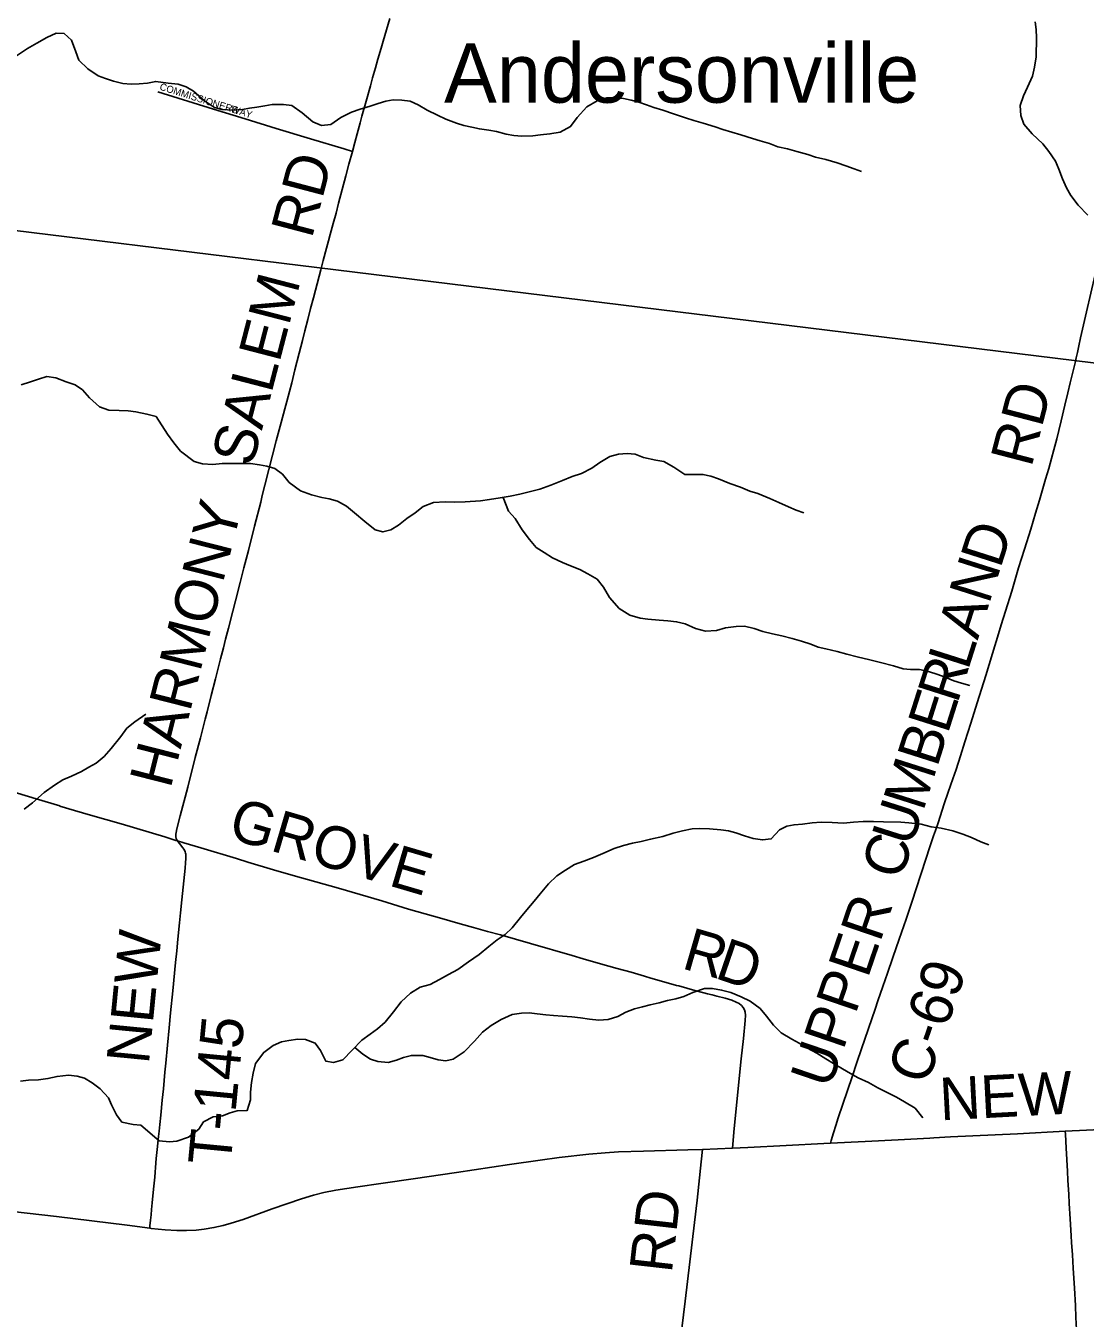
# Model space of a CAD drawing. Extents: x 1451455 to 1749751, y 218250 to 574981.
# Drawn here: x 1541480 to 1548942, y 371806 to 380909 of the extents above; entities that cross this region are included whole.
import ezdxf

# ---------------------------------------------------------------- set-up
doc = ezdxf.new("R2010")
doc.units = 0
for name, color, linetype in [('GM_X_County_Road', 7, 'Continuous'), ('GM_X_County_Road_Text', 7, 'Continuous'), ('GM_X_Minor_River', 7, 'Continuous'), ('GM_X_Township', 7, 'Continuous'), ('GM_X_Township_Road', 7, 'Continuous'), ('GM_X_Township_Road_Text', 7, 'Continuous'), ('GM_X_Township_Subdivision', 7, 'Continuous'), ('GM_X_Township_Subdivision_Text', 7, 'Continuous'), ('GM_X_Unincorporated_Text', 7, 'Continuous')]:
    doc.layers.add(name, color=color, linetype=linetype)

msp = doc.modelspace()

# ---------------------------------------------------------------- linework, layer by layer
at = {"layer": 'GM_X_County_Road'}
for points in [[(1548873.5, 378545.7), (1548879.2, 378569.3), (1548887.8, 378608.4), (1548897.9, 378654.2), (1548908.6, 378711.8), (1548922.1, 378772.3), (1548936.7, 378833.3), (1548958.7, 378925.8), (1548974.5, 378994.8), (1548988.8, 379056.9), (1549022.5, 379196.3), (1549040.4, 379268.8), (1549057.9, 379348.9), (1549072.7, 379416.2), (1549100.4, 379540), (1549121.8, 379635.1), (1549147.3, 379744.1), (1549180.4, 379885.5), (1549206.4, 379999), (1549236.1, 380128.4), (1549268.1, 380264.2), (1549292.4, 380367), (1549317, 380471.5)], [(1547147.2, 373038.2), (1547152.9, 373057.3), (1547169.4, 373112), (1547185, 373163.5), (1547202.1, 373217.2), (1547234.4, 373313.8), (1547300, 373505.5), (1547334.4, 373606.2), (1547367.2, 373703.5), (1547461.8, 373983.7), (1547480.9, 374041), (1547517, 374142.8), (1547548.5, 374235.3), (1547586.4, 374346.6), (1547630.5, 374476), (1547680, 374616.8), (1547721.7, 374735.3), (1547784.5, 374931.2), (1547822.6, 375047.3), (1547846.2, 375119.4), (1547874.4, 375202.6), (1547887.1, 375241), (1547905.2, 375296), (1547949.7, 375429.9), (1547977.7, 375510.7), (1548010.7, 375605.4), (1548032, 375669.7), (1548064.4, 375767.4), (1548094.8, 375865), (1548136, 375997.2), (1548180.5, 376141.3), (1548241.2, 376332.2), (1548289.5, 376488.7), (1548331.7, 376626.6), (1548351, 376690.7), (1548380, 376786.9), (1548424.1, 376927.7), (1548473.1, 377091.2), (1548514.8, 377222.4), (1548558.2, 377364), (1548592.1, 377476.4), (1548619.5, 377568.3), (1548662.6, 377715.6), (1548684.6, 377790.8), (1548705.6, 377862.3), (1548721.8, 377922.8), (1548742.8, 378000.7), (1548756.9, 378057.5), (1548773.3, 378125.9), (1548799.5, 378236.5), (1548820.3, 378323.4), (1548837.1, 378394), (1548850.7, 378451), (1548873.5, 378545.7)], [(1548801, 373122.4), (1549252.4, 373145.1), (1549350.6, 373149.5), (1549819.2, 373172.1), (1550087.9, 373185.7), (1550484.4, 373205.5), (1550772.6, 373219.9), (1551224.9, 373239.8), (1551618.1, 373259.5), (1551870.3, 373274.6), (1551912.6, 373278.1), (1552036.7, 373287.1), (1552088.9, 373291.6), (1552235.8, 373303.9), (1552340.2, 373313.9), (1552692.8, 373348.3), (1553146.4, 373394.4), (1553290.1, 373408.3), (1553476.1, 373426.5), (1553538.1, 373433.7), (1553560.3, 373435.7), (1553575.3, 373433.8), (1553584, 373430)], [(1547147.2, 373038.2), (1547391.6, 373050.4), (1547624.2, 373062.3), (1547846.9, 373074.6), (1547876.3, 373076.6), (1547994.1, 373082.6), (1548466, 373105.6), (1548801, 373122.4)], [(1546457.2, 373003.3), (1546565.4, 373007.7), (1546834.6, 373021.8), (1547100.1, 373035.8), (1547147.2, 373038.2)], [(1542353.1, 372440.2), (1542362.5, 372439), (1542460.7, 372429.1), (1542542.8, 372424.3), (1542611.9, 372424), (1542681, 372427.2), (1542736.7, 372433.2), (1542805, 372444.5), (1542869.4, 372458.2), (1542926.4, 372474.4), (1543010.7, 372502.3), (1543214.3, 372576), (1543421.8, 372648), (1543506.3, 372673.6), (1543579.4, 372691.3), (1543663, 372707), (1543818.5, 372730.9), (1543980.8, 372754.5), (1544224.2, 372791), (1544305.2, 372803), (1544513.1, 372832.9), (1544886.2, 372888.2), (1545103.7, 372919.9), (1545237, 372937.2), (1545445.5, 372960.9), (1545559.7, 372971.4), (1545654.5, 372977.2), (1545831.5, 372983.6), (1546142.7, 372992.4), (1546246.9, 372995.5)], [(1546101.2, 371734.6), (1546124.2, 371926.7), (1546189.4, 372480.7), (1546207.7, 372637), (1546236.4, 372907), (1546246.9, 372995.5)], [(1546246.9, 372995.5), (1546457.2, 373003.3)], [(1540435, 372667.6), (1540473.7, 372663.7), (1540515.7, 372659.5), (1540586.2, 372650.4), (1540751.6, 372630.6), (1540874, 372615.9), (1540971.8, 372605.3), (1541695.2, 372522), (1542193.4, 372461.5), (1542353.1, 372440.2)]]:
    msp.add_lwpolyline(points, dxfattribs=at)
at = {"layer": 'GM_X_Minor_River'}
for points in [[(1548590.6, 380937.3), (1548595.7, 380883.2), (1548598.7, 380825.1), (1548596.5, 380691.1), (1548585.3, 380617.2), (1548570.3, 380555.4), (1548535.1, 380477.9), (1548508.1, 380416.3), (1548485, 380348.6), (1548487.8, 380276.6), (1548508.8, 380216.2), (1548567.6, 380149.2), (1548644.3, 380078), (1548685.4, 380023.3), (1548732.2, 379954.5), (1548755.2, 379898.1), (1548782.1, 379831.6), (1548811, 379767.1), (1548840, 379714.6), (1548892.8, 379645.8), (1548959.6, 379574.6)], [(1541407, 380691.9), (1541492, 380748.5), (1541558.7, 380787.5), (1541629.3, 380826.4), (1541693.9, 380857.3), (1541749.8, 380854.4), (1541803, 380807.4), (1541831.6, 380726.8), (1541854.5, 380666.3), (1541917.4, 380605.2), (1541990.5, 380555.9), (1542042.2, 380537), (1542097.9, 380520), (1542163.6, 380502.9), (1542221.5, 380497.9), (1542277.5, 380501), (1542337.6, 380506), (1542395.8, 380517), (1542483.8, 380504.5)], [(1542483.8, 380504.5), (1542553.6, 380497.4), (1542609.2, 380478.5), (1542660.7, 380449.6), (1542739.4, 380380.3), (1542808.5, 380333.2), (1542864.2, 380320.3), (1542938, 380315.1), (1543006, 380320), (1543056.1, 380329.2), (1543106.2, 380336.5), (1543164.2, 380345.5), (1543216.3, 380354.7), (1543294.2, 380355.5), (1543354, 380348.5), (1543427, 380295.3), (1543501.9, 380232.1), (1543563.4, 380207.1), (1543627.4, 380214.1), (1543698.1, 380263), (1543774.6, 380299.8), (1543834.9, 380320.8), (1543905.2, 380343.7), (1543961.4, 380360.8), (1544015.6, 380377.9), (1544067.7, 380387.1), (1544129.6, 380386.1), (1544187.3, 380377.2), (1544244.8, 380352.3), (1544308.2, 380315.2), (1544379.5, 380280.1), (1544438.9, 380251.1), (1544514.4, 380223.9), (1544566, 380207.1), (1544621.7, 380194.2), (1544675.5, 380183.3), (1544741.2, 380174.2), (1544795, 380165.4), (1544864.6, 380146.3), (1544916.4, 380137.4), (1544974.2, 380132.5), (1545052.1, 380133.3), (1545106.2, 380140.4), (1545172.2, 380147.3), (1545244.3, 380160.2), (1545316.8, 380199.1), (1545363.9, 380264.3), (1545431, 380339.3), (1545503.6, 380380.2), (1545571.8, 380401.1), (1545627.8, 380402.2), (1545689.6, 380397.2), (1545743.3, 380386.4), (1545797, 380371.5), (1545852.6, 380352.6), (1545904.3, 380333.8), (1545965.9, 380314.8), (1546041.3, 380289.5), (1546126.7, 380260.2), (1546184.4, 380243.2), (1546249.9, 380222.2), (1546335.4, 380196.8), (1546389, 380177.9), (1546452.6, 380160.9), (1546516.2, 380141.9), (1546597.7, 380114.6), (1546653.4, 380099.7), (1546719, 380080.6), (1546776.5, 380057.7), (1546844.2, 380042.6), (1546909.8, 380023.5), (1546987.3, 380002.3), (1547042.9, 379983.4), (1547114.6, 379968.3), (1547194, 379943), (1547255.6, 379922), (1547315.2, 379901), (1547366.8, 379882.2)], [(1541446.9, 378379.4), (1541513.2, 378400.3), (1541569.6, 378419.4), (1541627.9, 378438.5), (1541691.7, 378429.4), (1541765.2, 378402.1), (1541828.8, 378381), (1541880.2, 378344.1), (1541929.2, 378289.2), (1541998.1, 378225.9), (1542065.7, 378200.8), (1542137.6, 378199.6), (1542201.5, 378196.5)], [(1542201.5, 378196.5), (1542255.4, 378189.6), (1542333.1, 378174.2), (1542398.8, 378157.1)], [(1542398.8, 378157.1), (1542479, 378033.2), (1542522, 377972.5), (1542569, 377913.7), (1542665.6, 377840.1), (1542725.2, 377823.2), (1542797, 377818), (1542863.1, 377825), (1542937, 377825.8), (1542998.9, 377826.8), (1543062.8, 377825.8), (1543126.6, 377816.7), (1543178.4, 377807.9), (1543234, 377791), (1543287.3, 377752.1), (1543336.2, 377693.3), (1543415.2, 377634), (1543492.6, 377604.8), (1543564.2, 377587.6), (1543615.9, 377576.8), (1543675.6, 377559.8), (1543738.9, 377526.8), (1543796.1, 377479.8), (1543869, 377418.7), (1543941.9, 377359.5), (1543995.6, 377344.6), (1544051.7, 377359.7), (1544104.2, 377392.9), (1544164.9, 377437.9), (1544221.5, 377479.1), (1544278.1, 377522.2), (1544352.5, 377551), (1544434.4, 377555.7), (1544498.3, 377554.7), (1544574.2, 377555.5), (1544682.2, 377563.7), (1544746.3, 377572.7), (1544820.4, 377583.5), (1544892.5, 377596.4), (1544960.6, 377611.3), (1545101, 377645.1), (1545177.4, 377673.9), (1545259.8, 377706.6), (1545328.1, 377733.5), (1545394.4, 377756.5), (1545466.9, 377793.3), (1545523.5, 377832.5), (1545594.1, 377875.3), (1545654.3, 377892.4), (1545716.3, 377897.4), (1545772.1, 377892.5), (1545831.7, 377869.5), (1545917.2, 377850.2), (1545975, 377839.2), (1546044.2, 377800.1), (1546121.3, 377748.9), (1546175.2, 377748), (1546249.1, 377748.8), (1546304.8, 377737.9), (1546358.4, 377717), (1546437.8, 377685.8), (1546513.3, 377658.5), (1546578.7, 377631.5), (1546636.4, 377614.6), (1546721.7, 377579.2), (1546783.1, 377552.2), (1546852.5, 377521.1), (1546906.1, 377498.2), (1546959.7, 377479.3)], [(1544842.2, 377587.5), (1544880.7, 377490.5), (1544925.8, 377437.8), (1544976.4, 377358.9), (1545027.2, 377290.1), (1545074.3, 377235.3), (1545131.6, 377198.4), (1545190.9, 377161.4), (1545260.2, 377128.3), (1545317.8, 377105.3), (1545381.3, 377080.3), (1545438.7, 377049.4), (1545504, 377010.3), (1545549, 376955.5), (1545591.7, 376882.8), (1545658.4, 376805.7), (1545735.5, 376758.5), (1545807, 376737.3), (1545860.8, 376730.5), (1545940.6, 376723.2), (1546002.4, 376718.2), (1546064.2, 376711.2), (1546123.9, 376696.2), (1546197.3, 376665), (1546266.9, 376645.9), (1546344.9, 376650.7), (1546409, 376667.7), (1546483.1, 376678.5), (1546543.1, 376679.5), (1546610.7, 376664.4), (1546670.3, 376643.5), (1546739.9, 376626.3), (1546805.6, 376611.3), (1546877.2, 376594.1), (1546942.8, 376575.1), (1547008.3, 376554), (1547061.9, 376533.2), (1547115.6, 376520.3), (1547195.2, 376501), (1547262.8, 376483.9), (1547336.4, 376464.7), (1547423.9, 376443.3), (1547499.5, 376424.1), (1547591, 376400.6), (1547660.6, 376379.5), (1547712.4, 376374.7), (1547774.3, 376375.7), (1547828.1, 376362.8), (1547883.7, 376345.9), (1547943.3, 376325), (1548016.7, 376295.8), (1548070.3, 376278.9), (1548130, 376262)], [(1541469.1, 375392.1), (1541527.8, 375437.2), (1541609, 375508), (1541681.9, 375560.8), (1541740.6, 375597.9), (1541803, 375624.9), (1541871.6, 375657.8), (1541924.1, 375687), (1541974.6, 375716.2), (1542031.3, 375761.3), (1542080.3, 375818.6), (1542149.8, 375903.5), (1542192.8, 375960.9), (1542247.5, 376006.1), (1542324.5, 376060.9)], [(1542290.2, 373164.6), (1542419.1, 373055.4), (1542492.9, 373048.2), (1542542.9, 373053.4), (1542625.2, 373082.1), (1542698, 373137), (1542732.8, 373188.5), (1542799.3, 373225.4), (1542865.3, 373230.4), (1542919.6, 373251.5), (1542969.8, 373266.7), (1543039.7, 373269.6), (1543062.9, 373343.3), (1543063.8, 373399.3), (1543070.9, 373465.2), (1543082, 373533.1), (1543099.1, 373600.8), (1543156.3, 373678), (1543223, 373726.9), (1543281.3, 373752), (1543333.5, 373763.2), (1543395.5, 373772.2), (1543449.4, 373769.3), (1543518.9, 373744.2), (1543556, 373691.6), (1543592.7, 373617), (1543648.4, 373606), (1543712.6, 373625), (1543777.7, 373694), (1543846.8, 373765), (1543905.4, 373806.1), (1543957.9, 373845.2), (1544010.6, 373890.4), (1544069.7, 373963.5), (1544122.8, 374034.7), (1544189.7, 374095.7), (1544258.3, 374136.6), (1544328.6, 374157.5), (1544395.1, 374192.5), (1544457.5, 374227.5), (1544522, 374262.5), (1544598.8, 374315.3), (1544673.6, 374368.1), (1544742.4, 374425), (1544799.1, 374470.1), (1544855.6, 374509.3), (1544906.3, 374556.5), (1544965.5, 374629.6), (1545008.3, 374682.9), (1545061.2, 374744.1), (1545104, 374795.5), (1545161.1, 374864.6), (1545219.9, 374921.7), (1545280.5, 374962.7), (1545345.1, 375001.7), (1545411.3, 375024.7), (1545479.7, 375051.6), (1545544, 375078.6), (1545624.5, 375113.3), (1545690.8, 375136.3), (1545753, 375151.3), (1545815.1, 375164.3), (1545881.2, 375179.2), (1545967.5, 375199.9), (1546039.7, 375222.7), (1546105.9, 375239.7), (1546174, 375252.6), (1546226, 375255.8), (1546295.9, 375252.7), (1546375.6, 375245.4), (1546429.5, 375238.5), (1546481.1, 375223.7), (1546542.7, 375202.7), (1546602.3, 375185.7), (1546668.1, 375174.7), (1546730.1, 375181.7), (1546789.1, 375244.8), (1546841.4, 375272), (1546891.5, 375281.2), (1546951.5, 375286.2), (1547019.6, 375295.1), (1547081.6, 375300.1), (1547159.4, 375296.9), (1547239.2, 375293.6), (1547309.3, 375300.5), (1547379.2, 375305.4), (1547451.1, 375304.2), (1547521, 375301.1), (1547642.8, 375299.2), (1547700.6, 375296.3), (1547786.3, 375284.9), (1547856, 375267.8), (1547927.7, 375256.6), (1548009.3, 375239.3), (1548080.8, 375216.1), (1548140.3, 375191.2), (1548205.7, 375162.1), (1548263.3, 375139.2)], [(1543796.6, 373713.5), (1543853.1, 373664.8), (1543908.5, 373629.9), (1543960.1, 373613.1), (1544031.9, 373607.9), (1544090.1, 373623), (1544140.3, 373642.2), (1544196.5, 373657.3), (1544276.4, 373656), (1544328.1, 373643.2), (1544383.7, 373626.3), (1544439.5, 373619.4), (1544489.7, 373630.6), (1544568.4, 373683.4), (1544639.5, 373758.3), (1544696.5, 373821.4), (1544757.2, 373868.5), (1544827.8, 373909.4), (1544906.2, 373944.1), (1544972.3, 373955.1), (1545026.3, 373956.2), (1545082.1, 373949.3), (1545143.9, 373942.3), (1545197.7, 373937.5), (1545259.6, 373934.5), (1545325.4, 373929.4), (1545387.2, 373922.4), (1545451, 373913.4), (1545516.7, 373904.4), (1545582.7, 373909.3), (1545649, 373930.3), (1545705.4, 373961.4), (1545767.7, 373984.4), (1545823.9, 373999.5), (1545878, 374012.6), (1545940.2, 374027.7), (1546000.3, 374042.7), (1546058.5, 374055.8), (1546114.6, 374070.9), (1546179, 374099.9), (1546261.4, 374128.6), (1546317.3, 374127.7), (1546381, 374116.7), (1546446.6, 374099.6), (1546518, 374068.5), (1546581.5, 374039.4), (1546652.5, 373988.3), (1546697.6, 373933.5), (1546746.5, 373870.7), (1546801.5, 373815.8), (1546874.7, 373772.6), (1546926.1, 373743.8), (1546985.5, 373708.8), (1547050.8, 373671.7), (1547114, 373632.7), (1547169.4, 373599.8), (1547232.7, 373562.8), (1547288.1, 373529.8), (1547343.5, 373499), (1547414.9, 373465.8), (1547482.1, 373428.7), (1547541.6, 373397.7), (1547612.9, 373362.6), (1547670.3, 373329.6), (1547743.4, 373284.4), (1547798.2, 373217.5)], [(1541443.8, 373475.3), (1541499.9, 373482.4), (1541570, 373485.2), (1541636.1, 373494.1), (1541700.4, 373509.1), (1541780.5, 373517.8)], [(1541780.5, 373517.8), (1541842.4, 373510.7), (1541894.1, 373495.8), (1541947.5, 373462.9), (1542004.8, 373421.9), (1542061.7, 373358.8), (1542082.8, 373308.4), (1542119.6, 373237.6), (1542156.7, 373186.9), (1542236.3, 373169.6), (1542290.2, 373164.6)]]:
    msp.add_lwpolyline(points, dxfattribs=at)
at = {"layer": 'GM_X_Township'}
for points in [[(1560610.7, 396563.8), (1560083.8, 391183.3), (1560020.7, 390538.7), (1559582.3, 385863.6), (1559460, 384557.6), (1559442.3, 384369.1), (1559324.4, 383579.2), (1559200.4, 380762.2), (1558887.7, 378455.9), (1558782.7, 377336.1), (1558546.6, 377365), (1556931.9, 377563.1), (1548864.9, 378552.6), (1543530.3, 379207), (1540005.4, 379639.4), (1537304.8, 379989.6), (1537139.1, 380008.6), (1537157.3, 380191.1), (1537668.2, 384165.1), (1538304.6, 389185.1), (1538423.2, 390125.7), (1538437.6, 390209.5), (1538810.1, 393176.3), (1539082.9, 395731.5)], [(1564834.8, 376599), (1558782.7, 377336.1), (1558546.6, 377365), (1556931.9, 377563.1), (1548864.9, 378552.6), (1543530.3, 379207), (1540005.4, 379639.4), (1537304.8, 379989.6), (1537139.1, 380008.6), (1536205.4, 372784.7), (1535397.4, 366215.7), (1534972, 363185.5), (1534842.5, 361982.9), (1536828.8, 361723.6), (1542981.2, 360926.3), (1547068.8, 360384.5), (1549821.1, 359954.5), (1552783.2, 359472.3), (1557653, 358922.7), (1558521.9, 358823.9), (1560898.8, 358553.6)]]:
    msp.add_lwpolyline(points, dxfattribs=at)
at = {"layer": 'GM_X_Township_Road'}
for points in [[(1543780.4, 380024.5), (1543797, 380086.1), (1543813.5, 380147.7), (1543834.6, 380226.1), (1543847.4, 380273.7), (1543877.4, 380378.7), (1543906.8, 380485.9), (1543923.2, 380543.3), (1543943, 380612.7), (1543959.8, 380674), (1543982.2, 380752.7), (1543997, 380801.8), (1544045, 380960.1)], [(1543611.9, 379393.5), (1543624.6, 379440.2), (1543646.1, 379515.8), (1543666.1, 379589.2), (1543683.7, 379659.6), (1543709.4, 379757.1), (1543734, 379851.5), (1543756.4, 379934.9), (1543780.4, 380024.5)], [(1543557.7, 379190), (1543574.7, 379255.9), (1543598.5, 379343.9), (1543611.9, 379393.5)], [(1542548.6, 375168), (1542543.7, 375175.4), (1542539.3, 375184.7), (1542536.3, 375196.7), (1542535.7, 375206.2), (1542536.1, 375216.4), (1542538, 375226), (1542544.4, 375251.9), (1542567.3, 375344.1), (1542620.8, 375546.5), (1542673.7, 375756.5), (1542710.2, 375895), (1542744.1, 376025.9), (1542756.6, 376076), (1542785.5, 376191.2), (1542815.5, 376310.1), (1542852, 376451.3), (1542871.5, 376527.2), (1542887.5, 376589.9), (1542907.4, 376667.3), (1542937.7, 376785.1), (1542956.5, 376858.7), (1542989.5, 376988), (1543016.6, 377091.6), (1543048.4, 377212.8), (1543092, 377385.1), (1543134.6, 377553.6), (1543145.5, 377600.6), (1543163, 377674.3), (1543191.8, 377784.9), (1543244.2, 377985.1), (1543279.1, 378113.8), (1543304.8, 378211.4), (1543318.2, 378262.2), (1543336.5, 378332.6), (1543352.7, 378394.8), (1543375.7, 378485.8), (1543405.9, 378604.3), (1543428.5, 378693), (1543445.3, 378759.8), (1543465.6, 378840.8), (1543486.1, 378916.8), (1543506.6, 378993), (1543546.4, 379145.7), (1543557.7, 379190)], [(1539120.6, 376194.7), (1539140.8, 376188.6), (1539269.1, 376149.6), (1539457.2, 376091.8), (1539636.4, 376038.2), (1539884, 375961.9), (1540126.2, 375890.4), (1540352.6, 375822.7), (1540449.7, 375792.9), (1540618.6, 375743), (1540713.9, 375714.8), (1540886.9, 375663.6), (1541031.7, 375620.9), (1541263.8, 375550.2), (1541552.9, 375463.5), (1541719.6, 375413.9), (1541720.9, 375413.5), (1541822.9, 375382), (1541936.5, 375349.6), (1542150.6, 375287), (1542459.3, 375196.8), (1542537.4, 375171.7), (1542548.6, 375168)], [(1542353.1, 372440.2), (1542354.6, 372455.6), (1542358.5, 372496), (1542362.1, 372534.2), (1542365.9, 372571.8), (1542370.6, 372618.6), (1542378.1, 372692.3), (1542382.2, 372737), (1542387.9, 372798.6), (1542391, 372835.6), (1542393.7, 372867.4), (1542398.9, 372930.1), (1542405.3, 372995.5), (1542414.8, 373085.6), (1542418.8, 373124.2), (1542423.7, 373170.6), (1542430.5, 373235.6), (1542441, 373341.7), (1542448.9, 373421.8), (1542459.3, 373538.2), (1542465.9, 373603.1), (1542477.8, 373728.6), (1542489.3, 373850.2), (1542499.9, 373957.6), (1542515, 374111.3), (1542535.1, 374311.7), (1542543.1, 374392.7), (1542551.4, 374476.5), (1542562.8, 374591.8), (1542569.7, 374662.3), (1542578.7, 374753), (1542602.2, 374976.5), (1542605.5, 375014.1), (1542607.2, 375044.1), (1542607.5, 375065.2), (1542606.5, 375074.7), (1542605, 375082.3), (1542602.6, 375090), (1542599.5, 375097.1), (1542592.6, 375108.7), (1542585.4, 375119.3), (1542576.2, 375131.7), (1542571.5, 375138.6), (1542562.8, 375149.5), (1542552, 375162.8), (1542548.6, 375168)], [(1542548.6, 375168), (1542593.4, 375153.3), (1542713, 375118.6), (1542964.3, 375043.3), (1543043.4, 375018.9), (1543225.1, 374964.9), (1543363.7, 374925), (1543682.3, 374834.2), (1543987.8, 374745.1), (1544176, 374687.9), (1544352.7, 374637.9), (1544393.4, 374625.8), (1544538.5, 374584.8), (1544633.3, 374558.3), (1544731.1, 374530.8), (1544822.8, 374505.6), (1545034.3, 374445.7), (1545327.3, 374360.9), (1545405.9, 374337.8), (1545528.4, 374301.9), (1545644.9, 374269.2), (1545743.3, 374243.5), (1545837.4, 374214.7), (1545881.5, 374202.1), (1545956.8, 374180), (1546064, 374150.6), (1546079.7, 374146.3), (1546193.4, 374115.3), (1546256.6, 374098), (1546282, 374091.8), (1546313.5, 374083), (1546348.4, 374073.7), (1546405.6, 374059.1), (1546453.3, 374045.4), (1546484.4, 374033.2), (1546505.1, 374021.8), (1546520.9, 374008.6), (1546531.7, 373995.2), (1546541.8, 373977.1), (1546546.9, 373960.6), (1546549.2, 373940.3), (1546547.7, 373903.6), (1546534.5, 373776.1), (1546519, 373632.7), (1546470.1, 373143.1), (1546457.2, 373003.3)], [(1548880.1, 371725.7), (1548876.8, 371810.9), (1548872.5, 371894.9), (1548866.1, 372018.8), (1548857.7, 372159.4), (1548852.2, 372251.3), (1548845.9, 372339.6), (1548842.3, 372385.4), (1548835.1, 372506.6), (1548829.2, 372614.8), (1548825.8, 372680.3), (1548820.6, 372775.2), (1548816.6, 372840.8), (1548807.6, 373002.6), (1548802.1, 373102.9), (1548801, 373122.4)]]:
    msp.add_lwpolyline(points, dxfattribs=at)
at = {"layer": 'GM_X_Township_Subdivision'}
msp.add_lwpolyline([(1542409.3, 380445.1), (1542802.2, 380322.7), (1543025.4, 380254), (1543244.6, 380186.2), (1543486, 380113.3), (1543722.2, 380042.1), (1543780.4, 380024.5)], dxfattribs=at)

# ---------------------------------------------------------------- texts
at = {"layer": 'GM_X_County_Road_Text'}
for s, rotation, p in [('RD', 75.41744, (1548562.4, 377792.4)), ('D', 72.25394, (1548344.1, 377080.6)), ('N', 72.34956, (1548264.1, 376829.1)), ('A', 72.3543, (1548184.1, 376577.5)), ('L', 72.35287, (1548116.1, 376363.7)), ('R', 72.3519, (1548041.4, 376128.9)), ('E', 72.35549, (1547973.3, 375915.1)), ('B', 72.3519, (1547898.6, 375680.2)), ('M', 72.35384, (1547799.9, 375370)), ('U', 72.35413, (1547719.9, 375118.4)), ('C', 72.35376, (1547645.2, 374883.6)), ('UPPER', 71.14662, (1547143.6, 373413.5)), ('C-69', 71.04091, (1547827.5, 373439.3)), ('NEW', 3.01339, (1547923.2, 373199)), ('RD', 83.55031, (1546029.4, 372117.7))]:
    msp.add_text(s, height=300, rotation=rotation, dxfattribs=at).set_placement(p)
at = {"layer": 'GM_X_Township_Road_Text'}
for s, rotation, p in [('RD', 75.25723, (1543494, 379403.6)), ('SALEM', 75.47256, (1543075.6, 377796.5)), ('HARMONY', 75.73983, (1542499, 375530)), ('GROVE', 343.56856, (1542894.2, 375190.4)), ('NEW', 84.40572, (1542346.5, 373589.7)), ('R', 343.87125, (1546091.4, 374272.5)), ('D', 341.02997, (1546324.4, 374205.3)), ('T-145', 84.51039, (1542921.1, 372874.2))]:
    msp.add_text(s, height=300, rotation=rotation, dxfattribs=at).set_placement(p)
at = {"layer": 'GM_X_Township_Subdivision_Text'}
for s, rotation, p in [('COMMISSIONERS', 342.52685, (1542418.4, 380460.2)), ('WAY', 342.6485, (1542919.9, 380301.8))]:
    msp.add_text(s, height=50, rotation=rotation, dxfattribs=at).set_placement(p)
at = {"layer": 'GM_X_Unincorporated_Text'}
msp.add_text('Andersonville', height=417, rotation=0.00001, dxfattribs=at).set_placement((1544425.9, 380367.5))

doc.saveas('drawing.dxf')
